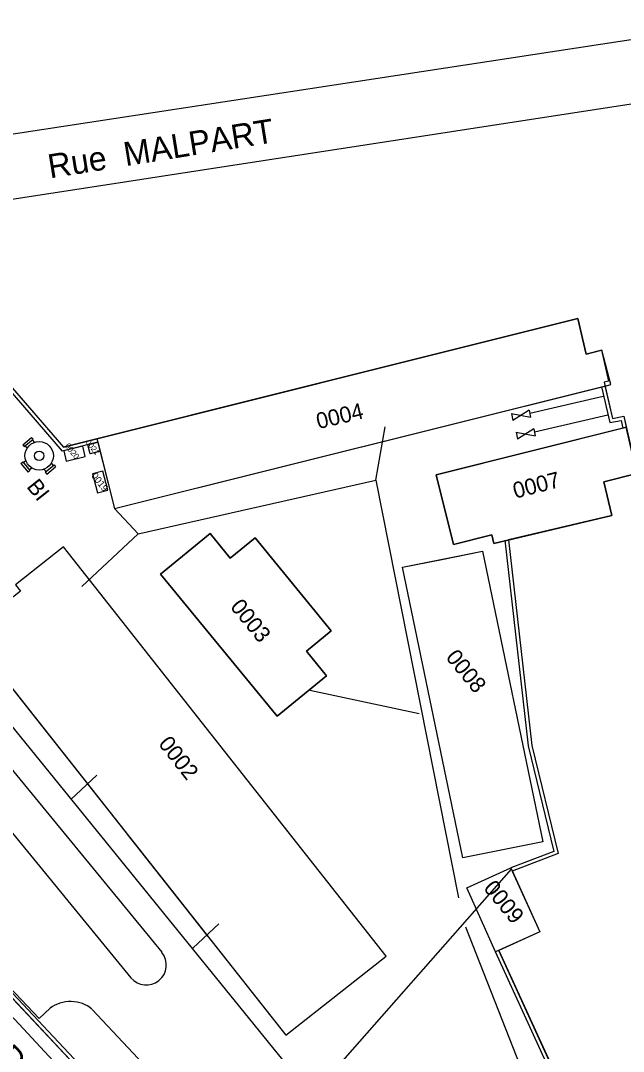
# Model space of a CAD drawing. Extents: x 703432 to 707394, y 7057985 to 7059523.
# Drawn here: x 704236.8 to 704312.2, y 7058728.3 to 7058857.2 of the extents above; entities that cross this region are included whole.
import ezdxf

# ---------------------------------------------------------------- set-up
doc = ezdxf.new("R2010")
doc.units = 0
for name, color, linetype in [('DH_HACHURE-MOTIF', 7, 'Continuous'), ('DH_TEXTE', 7, 'Continuous'), ('GEOSID_AIRE_AMENAGEE_POLYGONE', 7, 'Continuous'), ('GO_DALLE', 7, 'Continuous'), ('GO_MUR_EXTERIEUR', 7, 'Continuous'), ('IMM_LIMITE PHYSIQUE', 7, 'Continuous'), ('R_EPR_AEP_CANALISATION_CL_A', 7, 'Continuous'), ('R_PLU_CANALISATION_CL_A', 7, 'Continuous'), ('RES_INCENDIE - EQUIP - TEXTE', 7, 'Continuous'), ('SID_NUMERO_BATI', 7, 'Continuous'), ('SID_POLYLIGNES_BATI', 7, 'Continuous'), ('SID_POLYLIGNES_IMMEUBLE', 7, 'Continuous'), ('VOIRIE_BORDURE', 7, 'Continuous'), ('VOIRIE_ROUTE', 7, 'Continuous')]:
    doc.layers.add(name, color=color, linetype=linetype)

msp = doc.modelspace()

# ---------------------------------------------------------------- linework, layer by layer
at = {"layer": 'DH_HACHURE-MOTIF'}
for p, q in [((704284.59, 7058788.85), (704289.5, 7058789.81)), ((704292.13, 7058752.52), (704284.59, 7058788.85)), ((704302.15, 7058754.53), (704292.13, 7058752.52)), ((704292.62, 7058748.76), (704298.15, 7058751.26)), ((704296.23, 7058740.77), (704292.62, 7058748.76)), ((704301.76, 7058743.27), (704296.23, 7058740.77))]:
    msp.add_line(p, q, dxfattribs=at)
for points in [[(704246.5, 7058804.49), (704246.78, 7058803.35), (704248.57, 7058796.19), (704310.22, 7058811.6), (704310.66, 7058811.71), (704309.51, 7058815.99), (704307.57, 7058815.5), (704306.54, 7058819.95), (704269.67, 7058810.74), (704246.39, 7058804.92), (704246.5, 7058804.49)], [(704295.77, 7058792.9), (704296.01, 7058791.84), (704310.76, 7058795.32), (704309.76, 7058799.54), (704313.9, 7058800.57), (704312.57, 7058806.37), (704312.14, 7058806.26), (704288.79, 7058800.42), (704290.98, 7058791.69), (704295.77, 7058792.9)], [(704244.61, 7058804.01), (704242.23, 7058803.42), (704242.55, 7058802.13), (704244.93, 7058802.72), (704244.61, 7058804.01)], [(704246.44, 7058798.17), (704247.73, 7058798.5), (704247.13, 7058800.87), (704245.84, 7058800.55), (704246.44, 7058798.17)], [(704263.06, 7058789.97), (704260.53, 7058793.07), (704254.34, 7058788), (704268.92, 7058770.21), (704275.11, 7058775.28), (704272.57, 7058778.37), (704275.66, 7058780.91), (704266.16, 7058792.51), (704263.06, 7058789.97)], [(704282.57, 7058740.22), (704242.19, 7058791.4), (704236.19, 7058786.66), (704236.81, 7058785.87), (704230.25, 7058780.7), (704270.01, 7058730.31), (704282.57, 7058740.22)], [(704289.5, 7058789.81), (704294.61, 7058790.87), (704302.15, 7058754.53)], [(704298.15, 7058751.26), (704298.24, 7058751.07), (704301.76, 7058743.27)]]:
    msp.add_lwpolyline(points, dxfattribs=at)
at = {"layer": 'GEOSID_AIRE_AMENAGEE_POLYGONE'}
msp.add_lwpolyline([(704245.52, 7058803.03), (704245.24, 7058804.17), (704246.49, 7058804.49), (704246.78, 7058803.34)], close=True, dxfattribs=at)
at = {"layer": 'GO_DALLE'}
msp.add_lwpolyline([(704246.5, 7058804.49), (704246.78, 7058803.35), (704245.52, 7058803.03), (704245.24, 7058804.17)], close=True, dxfattribs=at)
at = {"layer": 'GO_MUR_EXTERIEUR'}
for p, q in [((704306.54, 7058819.95), (704246.39, 7058804.92)), ((704307.57, 7058815.5), (704306.54, 7058819.95)), ((704309.51, 7058815.99), (704307.57, 7058815.5)), ((704310.66, 7058811.71), (704309.51, 7058815.99)), ((704248.57, 7058796.19), (704310.66, 7058811.71)), ((704288.79, 7058800.42), (704312.57, 7058806.37)), ((704246.39, 7058804.92), (704248.57, 7058796.19)), ((704290.98, 7058791.69), (704288.79, 7058800.42)), ((704313.9, 7058800.57), (704309.76, 7058799.54)), ((704309.76, 7058799.54), (704310.76, 7058795.32)), ((704254.34, 7058788), (704260.53, 7058793.07)), ((704260.53, 7058793.07), (704263.06, 7058789.97)), ((704263.06, 7058789.97), (704266.16, 7058792.51)), ((704266.16, 7058792.51), (704275.66, 7058780.91)), ((704242.19, 7058791.4), (704236.19, 7058786.66)), ((704282.57, 7058740.22), (704242.19, 7058791.4)), ((704284.59, 7058788.85), (704294.61, 7058790.87)), ((704294.61, 7058790.87), (704302.15, 7058754.53)), ((704268.92, 7058770.21), (704254.34, 7058788)), ((704292.13, 7058752.52), (704284.59, 7058788.85)), ((704230.25, 7058780.7), (704270.01, 7058730.31)), ((704275.66, 7058780.91), (704272.57, 7058778.37)), ((704272.57, 7058778.37), (704275.11, 7058775.28)), ((704275.11, 7058775.28), (704268.92, 7058770.21)), ((704302.15, 7058754.53), (704292.13, 7058752.52)), ((704292.62, 7058748.76), (704298.15, 7058751.26)), ((704298.15, 7058751.26), (704301.76, 7058743.27)), ((704296.23, 7058740.77), (704292.62, 7058748.76)), ((704301.76, 7058743.27), (704296.23, 7058740.77)), ((704270.01, 7058730.31), (704282.57, 7058740.22))]:
    msp.add_line(p, q, dxfattribs=at)
for points in [[(704242.23, 7058803.42), (704242.55, 7058802.13), (704244.93, 7058802.72), (704244.61, 7058804.01)], [(704247.13, 7058800.87), (704245.84, 7058800.55), (704246.44, 7058798.17), (704247.73, 7058798.5)]]:
    msp.add_lwpolyline(points, close=True, dxfattribs=at)
msp.add_lwpolyline([(704310.76, 7058795.32), (704296.01, 7058791.84), (704295.77, 7058792.9), (704290.98, 7058791.69)], dxfattribs=at)
at = {"layer": 'IMM_LIMITE PHYSIQUE'}
for p, q in [((704230.31, 7058816.9), (704242.05, 7058803.37)), ((704230.65, 7058817.19), (704242.2, 7058803.87)), ((704246.51, 7058804.49), (704242.05, 7058803.37)), ((704246.39, 7058804.92), (704242.2, 7058803.87)), ((704203.53, 7058769.79), (704267.13, 7058702.37)), ((704203.2, 7058769.48), (704266.9, 7058701.96))]:
    msp.add_line(p, q, dxfattribs=at)
for points in [[(704309.47, 7058811.42), (704310.52, 7058806.94), (704311.92, 7058807.21), (704312.13, 7058806.26)], [(704309.91, 7058811.52), (704310.86, 7058807.46), (704312.26, 7058807.73), (704312.57, 7058806.37)], [(704297.39, 7058792.22), (704300.31, 7058766.5), (704303.54, 7058753.32), (704298.16, 7058751.26)], [(704297.84, 7058792.27), (704300.76, 7058766.57), (704304.07, 7058753.04), (704298.32, 7058750.84)], [(704305.17, 7058716.12), (704304.14, 7058723.47), (704296.24, 7058740.75)], [(704305.62, 7058716.18), (704304.58, 7058723.59), (704296.65, 7058740.93)]]:
    msp.add_lwpolyline(points, dxfattribs=at)
at = {"layer": 'R_EPR_AEP_CANALISATION_CL_A'}
for p, q in [((704309.69, 7058810.22), (704300.51, 7058808.06)), ((704300.43, 7058808.5), (704298.39, 7058807.19)), ((704300.43, 7058808.5), (704300.6, 7058807.62)), ((704298.22, 7058808.07), (704298.39, 7058807.19)), ((704298.22, 7058808.07), (704300.6, 7058807.62)), ((704310.27, 7058807.89), (704301.1, 7058805.73)), ((704281.25, 7058799.75), (704282.44, 7058806.4)), ((704301.01, 7058806.17), (704298.98, 7058804.86)), ((704301.01, 7058806.17), (704301.19, 7058805.29)), ((704298.8, 7058805.74), (704298.98, 7058804.86)), ((704298.8, 7058805.74), (704301.19, 7058805.29)), ((704281.25, 7058799.75), (704291.6, 7058747.49)), ((704251.54, 7058793.01), (704244.5, 7058786.45)), ((704272.99, 7058773.48), (704286.68, 7058770.57)), ((704243.12, 7058759.82), (704246.37, 7058762.84)), ((704266.57, 7058715.15), (704298.24, 7058751.07)), ((704258.36, 7058741.22), (704261.61, 7058744.25)), ((704300.63, 7058723.25), (704292.51, 7058743.82))]:
    msp.add_line(p, q, dxfattribs=at)
for points in [[(704248.57, 7058796.19), (704251.54, 7058793.01), (704281.25, 7058799.75)], [(704218.29, 7058779.15), (704227.29, 7058771.34), (704232.63, 7058772.76), (704273.17, 7058722.82)]]:
    msp.add_lwpolyline(points, dxfattribs=at)
at = {"layer": 'R_PLU_CANALISATION_CL_A'}
msp.add_line((704250.13, 7058755.5), (704260.25, 7058742.68), dxfattribs=at)
at = {"layer": 'RES_INCENDIE - EQUIP - TEXTE'}
for p, q in [((704237.11, 7058804.18), (704238.21, 7058805.08)), ((704237.3, 7058803.95), (704238.4, 7058804.85)), ((704238.21, 7058805.08), (704238.4, 7058804.85)), ((704238.3, 7058804.77), (704238.56, 7058804.46)), ((704237.11, 7058804.18), (704237.3, 7058803.95)), ((704237.39, 7058804.02), (704237.64, 7058803.71)), ((704236.88, 7058801.84), (704237.11, 7058802.03)), ((704237.11, 7058802.03), (704238.01, 7058800.93)), ((704237.18, 7058801.94), (704237.49, 7058802.19)), ((704236.88, 7058801.84), (704237.78, 7058800.74)), ((704237.78, 7058800.74), (704238.01, 7058800.93)), ((704237.93, 7058801.02), (704238.24, 7058801.27)), ((704239.76, 7058801.12), (704240.02, 7058800.81)), ((704239.93, 7058800.74), (704241.03, 7058801.64)), ((704239.93, 7058800.74), (704240.11, 7058800.51)), ((704240.11, 7058800.51), (704241.21, 7058801.41)), ((704240.68, 7058801.87), (704240.93, 7058801.56)), ((704241.03, 7058801.64), (704241.21, 7058801.41))]:
    msp.add_line(p, q, dxfattribs=at)
for radius in [1.78, 0.593]:
    msp.add_circle((704239.16, 7058802.79), radius, dxfattribs=at)
at = {"layer": 'SID_POLYLIGNES_BATI'}
for p, q in [((704306.54, 7058819.95), (704246.39, 7058804.92)), ((704307.57, 7058815.5), (704306.54, 7058819.95)), ((704309.51, 7058815.99), (704307.57, 7058815.5)), ((704310.66, 7058811.71), (704309.51, 7058815.99)), ((704248.57, 7058796.19), (704310.66, 7058811.71)), ((704246.39, 7058804.92), (704248.57, 7058796.19)), ((704254.34, 7058788), (704260.53, 7058793.07)), ((704260.53, 7058793.07), (704263.06, 7058789.97)), ((704263.06, 7058789.97), (704266.16, 7058792.51)), ((704266.16, 7058792.51), (704275.66, 7058780.91)), ((704242.19, 7058791.4), (704236.19, 7058786.66)), ((704282.57, 7058740.22), (704242.19, 7058791.4)), ((704284.59, 7058788.85), (704294.61, 7058790.87)), ((704294.61, 7058790.87), (704302.15, 7058754.53)), ((704268.92, 7058770.21), (704254.34, 7058788)), ((704292.13, 7058752.52), (704284.59, 7058788.85)), ((704230.25, 7058780.7), (704270.01, 7058730.31)), ((704275.66, 7058780.91), (704272.57, 7058778.37)), ((704272.57, 7058778.37), (704275.11, 7058775.28)), ((704275.11, 7058775.28), (704268.92, 7058770.21)), ((704302.15, 7058754.53), (704292.13, 7058752.52)), ((704292.62, 7058748.76), (704298.15, 7058751.26)), ((704298.15, 7058751.26), (704301.76, 7058743.27)), ((704296.23, 7058740.77), (704292.62, 7058748.76)), ((704301.76, 7058743.27), (704296.23, 7058740.77)), ((704270.01, 7058730.31), (704282.57, 7058740.22))]:
    msp.add_line(p, q, dxfattribs=at)
for points in [[(704245.52, 7058803.03), (704245.24, 7058804.17), (704246.5, 7058804.49), (704246.78, 7058803.35)], [(704242.23, 7058803.42), (704242.55, 7058802.13), (704244.93, 7058802.72), (704244.61, 7058804.01)], [(704247.13, 7058800.87), (704245.84, 7058800.55), (704246.44, 7058798.17), (704247.73, 7058798.5)]]:
    msp.add_lwpolyline(points, close=True, dxfattribs=at)
at = {"layer": 'SID_POLYLIGNES_IMMEUBLE'}
for p, q in [((704242.2, 7058803.87), (704306.54, 7058819.95)), ((704306.54, 7058819.95), (704307.57, 7058815.5)), ((704307.57, 7058815.5), (704309.47, 7058815.98)), ((704242.2, 7058803.87), (704242.2, 7058803.87)), ((704313.9, 7058800.57), (704309.76, 7058799.54)), ((704309.76, 7058799.54), (704310.76, 7058795.32)), ((704266.9, 7058701.96), (704177.69, 7058796.52)), ((704310.76, 7058795.32), (704297.84, 7058792.27)), ((704304.07, 7058753.04), (704298.32, 7058750.84)), ((704298.32, 7058750.84), (704301.76, 7058743.27)), ((704301.76, 7058743.27), (704296.65, 7058740.93)), ((704296.65, 7058740.93), (704304.58, 7058723.59))]:
    msp.add_line(p, q, dxfattribs=at)
for points in [[(704223.34, 7058829.27), (704224.1, 7058824.74), (704242.2, 7058803.87)], [(704309.47, 7058815.98), (704310.37, 7058812.14), (704309.8, 7058811.99), (704310.86, 7058807.46), (704312.26, 7058807.73), (704313.9, 7058800.57)], [(704297.84, 7058792.27), (704300.76, 7058766.57), (704304.07, 7058753.04)]]:
    msp.add_lwpolyline(points, dxfattribs=at)
at = {"layer": 'VOIRIE_BORDURE'}
for p, q in [((704235.05, 7058764.42), (704254.5, 7058740.69)), ((704231.18, 7058761.25), (704250.63, 7058737.52)), ((704221.22, 7058751.41), (704239.15, 7058732.4)), ((704239.15, 7058732.4), (704240.54, 7058733.71)), ((704245.77, 7058733.56), (704256.04, 7058722.67))]:
    msp.add_line(p, q, dxfattribs=at)
msp.add_arc((704252.56, 7058739.1), 2.5, 219.3307, 39.3307, dxfattribs=at)
msp.add_ellipse((704243.07, 7058731.53), major_axis=(-3.68, 0), ratio=0.816097, start_param=3.897855, end_param=5.468654, dxfattribs=at)
at = {"layer": 'VOIRIE_ROUTE'}
msp.add_line((704213.46, 7058756.55), (704265.78, 7058700.48), dxfattribs=at)
for points in [[(704170.12, 7058811.18), (704197.35, 7058833.54), (704203.38, 7058836.84), (704211.84, 7058839.38), (704328.73, 7058857.21)], [(704329.98, 7058849.33), (704212.69, 7058831.3), (704203.33, 7058827.34), (704175.74, 7058804.96)]]:
    msp.add_lwpolyline(points, dxfattribs=at)

# ---------------------------------------------------------------- texts
at = {"layer": 'DH_TEXTE'}
for s, rotation, p in [('Rue  MALPART', 9.1668, (704240.51, 7058837.47)), ('Rue LYDERIC', 313.8024, (704224.4, 7058737.04))]:
    msp.add_text(s, height=3, rotation=rotation, dxfattribs=at).set_placement(p)
at = {"layer": 'RES_INCENDIE - EQUIP - TEXTE'}
msp.add_text('BI', height=1.975, rotation=308.2727, dxfattribs=at).set_placement((704237.51, 7058798.91))
at = {"layer": 'SID_NUMERO_BATI'}
for s, height, rotation, p in [('0004', 2, 13.5243, (704274.08, 7058806.11)), ('0021', 0.702, 308.0308, (704244.93, 7058804.47)), ('0020', 0.738, 308.0308, (704242.32, 7058804.01)), ('0019', 0.866, 308.0308, (704245.62, 7058800.26)), ('0007', 2, 14.5051, (704298.7, 7058797.42)), ('0003', 2, 309.3307, (704262.96, 7058783.86)), ('0008', 2, 309.3307, (704289.91, 7058777.54)), ('0002', 2, 308.2727, (704253.98, 7058766.74)), ('0009', 2, 309.3307, (704294.63, 7058748.68))]:
    msp.add_text(s, height=height, rotation=rotation, dxfattribs=at).set_placement(p)

doc.saveas('drawing.dxf')
